// Mitsubishi GX Works2 project: TEST   PLC: Q00J

PROGRAM MAIN
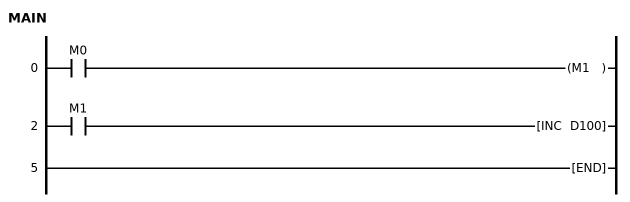
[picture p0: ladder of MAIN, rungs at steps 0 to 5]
0     LD      M0
      OUT     M1
2     LD      M1
      INC     D100
5     END
END_PROGRAM
